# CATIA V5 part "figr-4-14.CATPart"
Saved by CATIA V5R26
Part number: Part1
Bounding box of the stored display mesh (mm): x -69.981 to 69.981, y -240 to 0, z -69.908 to 69.908
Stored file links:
  D:\_Deepak\CATIA\CATIA V5-6R2016_Deepak\Resources\Part files\Partfiles\c04_catia_v5_6r2016_prt\figr-4-14.CATPart
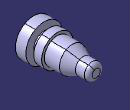
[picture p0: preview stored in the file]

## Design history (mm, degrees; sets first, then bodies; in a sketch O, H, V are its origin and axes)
Body1 (main body)
  Sketch1 on yz-plane, origin (0, 0, 0), H (0, 1, 0), V (0, 0, 1)
    line L1 (0, 0) -> (0, 15.359)
    arc A1 centre (-15.359, 15.359) radius 15.359 from (0, 15.359) to (-15.359, 30.718) ccw
    point P2 (-15.359, 15.359)
    line L2 (-15.359, 30.718) -> (-49.6877, 30.718)
    line L3 (-49.6877, 30.718) -> (-91.8922, 49.6007)
    line L4 (-91.8922, 49.6007) -> (-149.3038, 49.6007)
    line L5 (-149.3038, 49.6007) -> (-149.3038, 60)
    line L6 (-149.3038, 60) -> (-180, 60)
    line L7 (-180, 60) -> (-180, 38.9967)
    line L8 (-180, 38.9967) -> (-200, 40)
    line L9 (-200, 40) -> (-200, 70)
    line L10 (-200, 70) -> (-240, 70)
    line L11 (-240, 70) -> (-240, 0)
    line L12 (-240, 0) -> (0, 0)
    axis line L13 (-300, 0) -> (50, 0)
    vertical: L1 V, L5 V, L7 V, L9 V, L11 V
    tangency: A1 L1, L2 A1, L8 A1, L12 A1, L13 A1
    coincidence: L3 P2
    horizontal: L4 H, L6 H, L10 H, L2 H
    fix: L12
  Shaft1: profile Sketch1, axis Sketch1.H, angle 360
